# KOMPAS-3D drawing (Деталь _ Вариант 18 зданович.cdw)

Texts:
  Вариант 18
  СК 1
  СК 2
  СК 3
  зданович
  Подгорный
  Сталь
  Вариант 18-
Dimensions and other numbers on the sheet: 60; 55; 20; 5; 50; 70; 40; 85; 65; 30; 15; 1:1; 1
